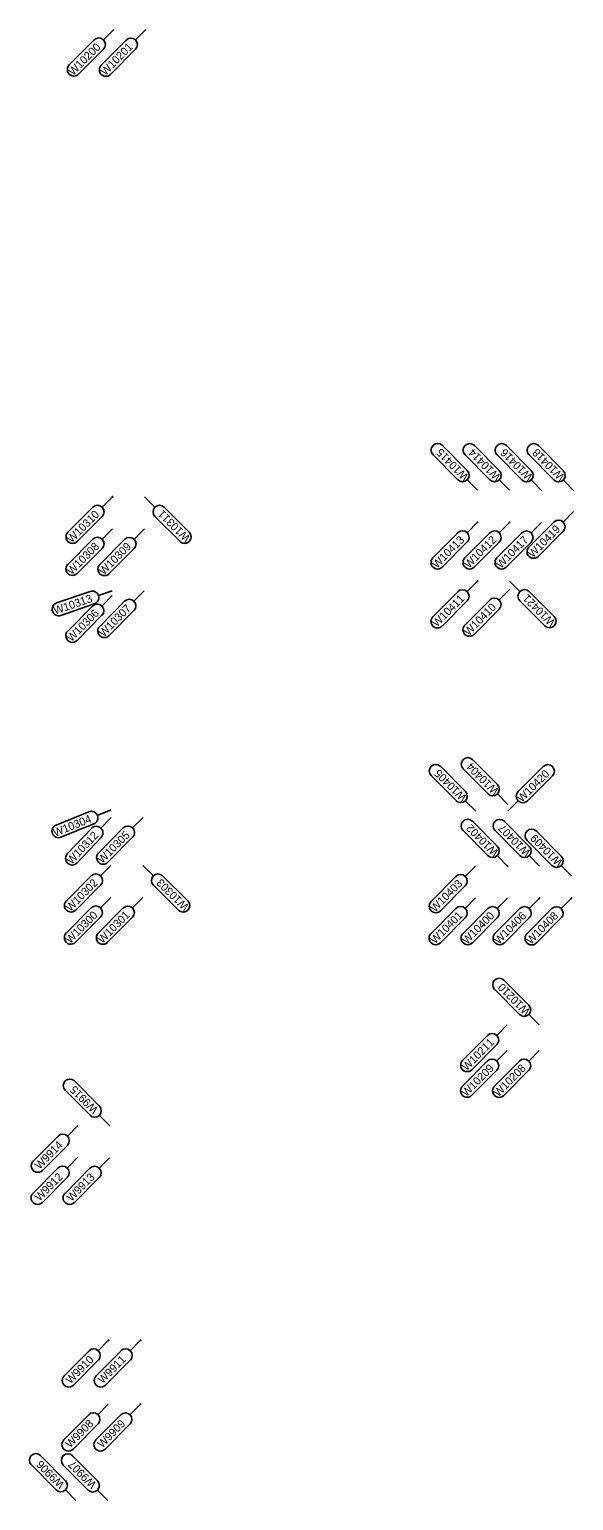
# Model space of a CAD drawing. Extents: x 12479652 to 12487250, y 9842710 to 9846560.
# Drawn here: x 12483667.3 to 12483752.3, y 9845145.7 to 9845375.4 of the extents above; entities that cross this region are included whole.
import ezdxf

# ---------------------------------------------------------------- set-up
doc = ezdxf.new("R2010")
doc.units = 0
doc.layers.add('Default', color=7, linetype='Continuous')
doc.layers.add('TextAlignmentLrg', color=7, linetype='Continuous')

msp = doc.modelspace()

# ---------------------------------------------------------------- linework, layer by layer
at = {"layer": 'Default'}
for p, q in [((12483673.52, 9845369.86), (12483677.41, 9845373.77)), ((12483678.52, 9845369.84), (12483682.41, 9845373.75)), ((12483680.48, 9845375.41), (12483678.86, 9845373.78)), ((12483685.48, 9845375.39), (12483683.86, 9845373.76)), ((12483678.87, 9845372.33), (12483674.98, 9845368.42)), ((12483683.87, 9845372.31), (12483679.98, 9845368.39)), ((12483735.7, 9845306.53), (12483731.82, 9845310.44)), ((12483740.7, 9845306.52), (12483736.82, 9845310.44)), ((12483745.7, 9845306.51), (12483741.82, 9845310.43)), ((12483750.7, 9845306.51), (12483746.82, 9845310.42)), ((12483730.36, 9845309), (12483734.25, 9845305.08)), ((12483735.36, 9845308.99), (12483739.25, 9845305.08)), ((12483740.36, 9845308.98), (12483744.25, 9845305.07)), ((12483745.36, 9845308.97), (12483749.25, 9845305.06)), ((12483737.32, 9845303.45), (12483735.7, 9845305.08)), ((12483742.32, 9845303.44), (12483740.7, 9845305.07)), ((12483747.32, 9845303.43), (12483745.7, 9845305.06)), ((12483752.32, 9845303.42), (12483750.7, 9845305.06)), ((12483680.27, 9845302.43), (12483678.65, 9845300.8)), ((12483685.27, 9845302.42), (12483686.9, 9845300.8)), ((12483673.31, 9845296.88), (12483677.2, 9845300.79)), ((12483688.35, 9845300.8), (12483692.26, 9845296.91)), ((12483752.32, 9845300.12), (12483750.69, 9845298.49)), ((12483678.65, 9845299.35), (12483674.76, 9845295.44)), ((12483690.82, 9845295.46), (12483686.91, 9845299.35)), ((12483737.31, 9845298.45), (12483735.69, 9845296.82)), ((12483742.31, 9845298.44), (12483740.69, 9845296.81)), ((12483745.35, 9845294.57), (12483749.24, 9845298.48)), ((12483747.31, 9845298.43), (12483745.69, 9845296.8)), ((12483673.3, 9845291.88), (12483677.19, 9845295.79)), ((12483678.3, 9845291.87), (12483682.19, 9845295.79)), ((12483680.26, 9845297.43), (12483678.64, 9845295.8)), ((12483685.26, 9845297.42), (12483683.64, 9845295.79)), ((12483730.35, 9845292.9), (12483734.24, 9845296.81)), ((12483735.7, 9845295.37), (12483731.81, 9845291.45)), ((12483735.35, 9845292.89), (12483739.24, 9845296.8)), ((12483740.7, 9845295.36), (12483736.81, 9845291.45)), ((12483740.35, 9845292.88), (12483744.24, 9845296.8)), ((12483745.7, 9845295.35), (12483741.81, 9845291.44)), ((12483750.7, 9845297.04), (12483746.81, 9845293.13)), ((12483678.65, 9845294.35), (12483674.76, 9845290.44)), ((12483683.65, 9845294.34), (12483679.76, 9845290.43)), ((12483737.3, 9845289.25), (12483735.68, 9845287.62)), ((12483742.3, 9845289.24), (12483743.93, 9845287.62)), ((12483671.54, 9845285.85), (12483676.76, 9845287.65)), ((12483680.23, 9845287.76), (12483678.06, 9845287.01)), ((12483680.23, 9845287), (12483678.61, 9845285.37)), ((12483685.23, 9845287.74), (12483683.61, 9845286.11)), ((12483730.34, 9845283.7), (12483734.23, 9845287.61)), ((12483735.68, 9845286.17), (12483731.79, 9845282.25)), ((12483735.34, 9845282.4), (12483739.23, 9845286.31)), ((12483742.3, 9845287.95), (12483740.68, 9845286.32)), ((12483747.85, 9845282.28), (12483743.94, 9845286.17)), ((12483745.38, 9845287.62), (12483749.29, 9845283.73)), ((12483677.42, 9845285.71), (12483672.21, 9845283.91)), ((12483673.27, 9845281.45), (12483677.16, 9845285.36)), ((12483678.61, 9845283.92), (12483674.73, 9845280)), ((12483678.27, 9845282.2), (12483682.16, 9845286.11)), ((12483683.62, 9845284.66), (12483679.73, 9845280.75)), ((12483740.68, 9845284.86), (12483736.79, 9845280.95)), ((12483740.41, 9845257.48), (12483736.52, 9845261.39)), ((12483730.06, 9845258.89), (12483733.95, 9845254.98)), ((12483735.41, 9845256.43), (12483731.52, 9845260.34)), ((12483735.07, 9845259.94), (12483738.96, 9845256.03)), ((12483747.58, 9845260.3), (12483743.66, 9845256.41)), ((12483745.11, 9845254.95), (12483749.02, 9845258.84)), ((12483737.03, 9845253.34), (12483735.4, 9845254.97)), ((12483742.03, 9845254.39), (12483740.41, 9845256.02)), ((12483742.03, 9845253.34), (12483743.66, 9845254.96)), ((12483671.45, 9845251.17), (12483676.57, 9845253.24)), ((12483680.04, 9845253.53), (12483677.9, 9845252.67)), ((12483680.04, 9845252.36), (12483678.45, 9845250.69)), ((12483685.04, 9845252.35), (12483683.41, 9845250.72)), ((12483740.4, 9845247.85), (12483736.51, 9845251.76)), ((12483745.4, 9845247.84), (12483741.51, 9845251.75)), ((12483677.34, 9845251.34), (12483672.22, 9845249.27)), ((12483673.2, 9845246.65), (12483677, 9845250.65)), ((12483678.07, 9845246.8), (12483681.96, 9845250.72)), ((12483735.05, 9845250.32), (12483738.94, 9845246.4)), ((12483740.05, 9845250.31), (12483743.94, 9845246.39)), ((12483750.39, 9845246.31), (12483746.5, 9845250.22)), ((12483678.49, 9845249.24), (12483674.69, 9845245.24)), ((12483683.42, 9845249.27), (12483679.53, 9845245.36)), ((12483745.05, 9845248.77), (12483748.94, 9845244.86)), ((12483680.02, 9845244.86), (12483678.4, 9845243.23)), ((12483685.02, 9845244.85), (12483686.66, 9845243.23)), ((12483742.01, 9845244.77), (12483740.39, 9845246.4)), ((12483747.01, 9845244.76), (12483745.39, 9845246.39)), ((12483752.01, 9845243.22), (12483750.39, 9845244.85)), ((12483673.06, 9845239.31), (12483676.95, 9845243.23)), ((12483688.11, 9845243.24), (12483692.02, 9845239.35)), ((12483730.05, 9845239.23), (12483733.94, 9845243.14)), ((12483737.01, 9845244.77), (12483735.39, 9845243.14)), ((12483678.41, 9845241.78), (12483674.52, 9845237.87)), ((12483690.57, 9845237.89), (12483686.66, 9845241.78)), ((12483735.4, 9845241.69), (12483731.51, 9845237.78)), ((12483673.05, 9845234.31), (12483676.94, 9845238.23)), ((12483678.05, 9845234.31), (12483681.94, 9845238.22)), ((12483680.02, 9845239.86), (12483678.4, 9845238.23)), ((12483685.02, 9845239.85), (12483683.4, 9845238.22)), ((12483730.04, 9845234.23), (12483733.93, 9845238.14)), ((12483735.04, 9845234.22), (12483738.93, 9845238.13)), ((12483737.01, 9845239.78), (12483735.38, 9845238.15)), ((12483740.04, 9845234.21), (12483743.93, 9845238.12)), ((12483742.01, 9845239.77), (12483740.38, 9845238.14)), ((12483745.04, 9845234.2), (12483748.93, 9845238.12)), ((12483747.01, 9845239.76), (12483745.38, 9845238.13)), ((12483752.01, 9845239.75), (12483750.38, 9845238.12)), ((12483678.4, 9845236.78), (12483674.51, 9845232.87)), ((12483683.4, 9845236.77), (12483679.51, 9845232.86)), ((12483735.39, 9845236.7), (12483731.5, 9845232.78)), ((12483740.39, 9845236.68), (12483736.5, 9845232.77)), ((12483745.39, 9845236.68), (12483741.5, 9845232.76)), ((12483750.39, 9845236.67), (12483746.5, 9845232.76)), ((12483745.33, 9845223.03), (12483741.44, 9845226.94)), ((12483739.99, 9845225.5), (12483743.87, 9845221.58)), ((12483741.95, 9845219.96), (12483740.33, 9845218.33)), ((12483746.95, 9845219.95), (12483745.33, 9845221.58)), ((12483734.98, 9845214.42), (12483738.87, 9845218.33)), ((12483740.33, 9845216.88), (12483736.44, 9845212.97)), ((12483741.94, 9845215.96), (12483740.31, 9845214.33)), ((12483746.94, 9845215.95), (12483745.31, 9845214.32)), ((12483734.97, 9845210.42), (12483738.86, 9845214.33)), ((12483740.32, 9845212.88), (12483736.43, 9845208.97)), ((12483739.97, 9845210.4), (12483743.86, 9845214.31)), ((12483745.32, 9845212.87), (12483741.43, 9845208.95)), ((12483678.22, 9845207.29), (12483674.33, 9845211.21)), ((12483672.88, 9845209.76), (12483676.77, 9845205.85)), ((12483679.84, 9845204.21), (12483678.22, 9845205.84)), ((12483674.84, 9845204.24), (12483673.22, 9845202.61)), ((12483667.88, 9845198.69), (12483671.77, 9845202.6)), ((12483673.22, 9845201.15), (12483669.33, 9845197.24)), ((12483674.81, 9845199.24), (12483673.19, 9845197.61)), ((12483679.81, 9845199.21), (12483678.19, 9845197.58)), ((12483667.85, 9845193.69), (12483671.74, 9845197.6)), ((12483672.85, 9845193.66), (12483676.74, 9845197.58)), ((12483673.2, 9845196.15), (12483669.31, 9845192.24)), ((12483678.2, 9845196.13), (12483674.31, 9845192.22)), ((12483672.71, 9845165.17), (12483676.6, 9845169.08)), ((12483677.71, 9845165.16), (12483681.6, 9845169.07)), ((12483679.67, 9845170.72), (12483678.05, 9845169.08)), ((12483684.67, 9845170.71), (12483683.05, 9845169.08)), ((12483678.05, 9845167.63), (12483674.16, 9845163.72)), ((12483683.05, 9845167.63), (12483679.16, 9845163.71)), ((12483679.62, 9845160.72), (12483678, 9845159.08)), ((12483684.62, 9845160.71), (12483683, 9845159.08)), ((12483672.66, 9845155.17), (12483676.55, 9845159.08)), ((12483678, 9845157.63), (12483674.11, 9845153.72)), ((12483677.66, 9845155.16), (12483681.55, 9845159.07)), ((12483683, 9845157.63), (12483679.11, 9845153.71)), ((12483667.59, 9845151.26), (12483671.47, 9845147.34)), ((12483672.93, 9845148.79), (12483669.04, 9845152.7)), ((12483672.58, 9845151.23), (12483676.47, 9845147.32)), ((12483677.93, 9845148.77), (12483674.04, 9845152.68)), ((12483674.55, 9845145.71), (12483672.93, 9845147.34)), ((12483679.55, 9845145.68), (12483677.93, 9845147.31))]:
    msp.add_line(p, q, dxfattribs=at)
for centre, start, end in [((12483678.14, 9845373.05), 315.1702, 135.1702), ((12483683.14, 9845373.03), 315.1702, 135.1702), ((12483674.25, 9845369.14), 135.1702, 315.1702), ((12483679.25, 9845369.12), 135.1702, 315.1702), ((12483731.09, 9845309.72), 44.8253, 224.8253), ((12483736.09, 9845309.71), 44.8253, 224.8253), ((12483741.09, 9845309.7), 44.8253, 224.8253), ((12483746.09, 9845309.7), 44.8253, 224.8253), ((12483734.98, 9845305.81), 224.8253, 44.8253), ((12483739.98, 9845305.8), 224.8253, 44.8253), ((12483744.98, 9845305.79), 224.8253, 44.8253), ((12483749.98, 9845305.78), 224.8253, 44.8253), ((12483677.93, 9845300.07), 315.1702, 135.1702), ((12483687.63, 9845300.07), 45.1702, 225.1702), ((12483749.97, 9845297.76), 315.1702, 135.1702), ((12483674.04, 9845296.16), 135.1702, 315.1702), ((12483677.92, 9845295.07), 315.1702, 135.1702), ((12483682.92, 9845295.06), 315.1702, 135.1702), ((12483691.54, 9845296.18), 225.1702, 45.1702), ((12483734.97, 9845296.09), 315.1702, 135.1702), ((12483739.97, 9845296.08), 315.1702, 135.1702), ((12483744.97, 9845296.07), 315.1702, 135.1702), ((12483746.08, 9845293.85), 135.1702, 315.1702), ((12483674.03, 9845291.16), 135.1702, 315.1702), ((12483679.03, 9845291.15), 135.1702, 315.1702), ((12483731.08, 9845292.18), 135.1702, 315.1702), ((12483736.08, 9845292.17), 135.1702, 315.1702), ((12483741.08, 9845292.16), 135.1702, 315.1702), ((12483677.09, 9845286.68), 289.0033, 109.0033), ((12483682.89, 9845285.39), 315.1702, 135.1702), ((12483734.95, 9845286.89), 315.1702, 135.1702), ((12483739.95, 9845285.59), 315.1702, 135.1702), ((12483744.66, 9845286.9), 45.1702, 225.1702), ((12483671.87, 9845284.88), 109.0033, 289.0033), ((12483677.89, 9845284.64), 315.1702, 135.1702), ((12483679, 9845281.47), 135.1702, 315.1702), ((12483731.07, 9845282.98), 135.1702, 315.1702), ((12483736.06, 9845281.68), 135.1702, 315.1702), ((12483748.57, 9845283.01), 225.1702, 45.1702), ((12483674, 9845280.73), 135.1702, 315.1702), ((12483735.79, 9845260.67), 44.8253, 224.8253), ((12483730.79, 9845259.61), 44.8253, 224.8253), ((12483748.3, 9845259.57), 314.8253, 134.8253), ((12483734.68, 9845255.7), 224.8253, 44.8253), ((12483739.68, 9845256.75), 224.8253, 44.8253), ((12483744.39, 9845255.68), 134.8253, 314.8253), ((12483676.95, 9845252.29), 291.9817, 111.9817), ((12483735.78, 9845251.04), 44.8253, 224.8253), ((12483740.78, 9845251.03), 44.8253, 224.8253), ((12483671.84, 9845250.22), 111.9817, 291.9817), ((12483677.75, 9845249.95), 316.4678, 136.4678), ((12483682.69, 9845249.99), 315.1702, 135.1702), ((12483745.78, 9845249.5), 44.8253, 224.8253), ((12483739.67, 9845247.13), 224.8253, 44.8253), ((12483744.67, 9845247.12), 224.8253, 44.8253), ((12483673.95, 9845245.95), 136.4678, 316.4678), ((12483678.8, 9845246.08), 135.1702, 315.1702), ((12483749.67, 9845245.58), 224.8253, 44.8253), ((12483677.68, 9845242.5), 315.1702, 135.1702), ((12483687.38, 9845242.51), 45.1702, 225.1702), ((12483734.67, 9845242.42), 315.1702, 135.1702), ((12483673.79, 9845238.59), 135.1702, 315.1702), ((12483677.67, 9845237.5), 315.1702, 135.1702), ((12483682.67, 9845237.49), 315.1702, 135.1702), ((12483691.3, 9845238.62), 225.1702, 45.1702), ((12483730.78, 9845238.5), 135.1702, 315.1702), ((12483734.66, 9845237.42), 315.1702, 135.1702), ((12483739.66, 9845237.41), 315.1702, 135.1702), ((12483744.66, 9845237.4), 315.1702, 135.1702), ((12483749.66, 9845237.39), 315.1702, 135.1702), ((12483673.78, 9845233.59), 135.1702, 315.1702), ((12483678.78, 9845233.58), 135.1702, 315.1702), ((12483730.77, 9845233.51), 135.1702, 315.1702), ((12483735.77, 9845233.5), 135.1702, 315.1702), ((12483740.77, 9845233.49), 135.1702, 315.1702), ((12483745.77, 9845233.48), 135.1702, 315.1702), ((12483740.71, 9845226.22), 44.8253, 224.8253), ((12483744.6, 9845222.31), 224.8253, 44.8253), ((12483739.6, 9845217.6), 315.1702, 135.1702), ((12483735.71, 9845213.69), 135.1702, 315.1702), ((12483739.59, 9845213.6), 315.1702, 135.1702), ((12483744.59, 9845213.59), 315.1702, 135.1702), ((12483673.6, 9845210.48), 44.8253, 224.8253), ((12483735.7, 9845209.69), 135.1702, 315.1702), ((12483740.7, 9845209.68), 135.1702, 315.1702), ((12483677.49, 9845206.57), 224.8253, 44.8253), ((12483672.49, 9845201.88), 315.1702, 135.1702), ((12483668.6, 9845197.97), 135.1702, 315.1702), ((12483672.47, 9845196.88), 315.1702, 135.1702), ((12483677.47, 9845196.85), 315.1702, 135.1702), ((12483668.58, 9845192.97), 135.1702, 315.1702), ((12483673.58, 9845192.94), 135.1702, 315.1702), ((12483677.33, 9845168.36), 315.1702, 135.1702), ((12483682.33, 9845168.35), 315.1702, 135.1702), ((12483673.44, 9845164.44), 135.1702, 315.1702), ((12483678.44, 9845164.44), 135.1702, 315.1702), ((12483677.28, 9845158.36), 315.1702, 135.1702), ((12483682.28, 9845158.35), 315.1702, 135.1702), ((12483668.31, 9845151.98), 44.8253, 224.8253), ((12483673.31, 9845151.96), 44.8253, 224.8253), ((12483673.39, 9845154.44), 135.1702, 315.1702), ((12483678.39, 9845154.44), 135.1702, 315.1702), ((12483672.2, 9845148.07), 224.8253, 44.8253), ((12483677.2, 9845148.04), 224.8253, 44.8253)]:
    msp.add_arc(centre, 1.03, start, end, dxfattribs=at)
at = {"layer": 'TextAlignmentLrg'}
for centre in [(12483680.27, 9845302.43), (12483737.32, 9845298.45), (12483742.31, 9845298.44), (12483737.3, 9845289.25), (12483742.01, 9845244.77), (12483747.01, 9845239.76), (12483752.01, 9845239.75), (12483679.67, 9845170.72), (12483684.67, 9845170.7), (12483684.62, 9845160.71)]:
    msp.add_circle(centre, 0.05, dxfattribs=at)

# ---------------------------------------------------------------- texts
at = {"layer": 'Default'}
for s, rotation, p in [('W10200', 45.1702, (12483674.13, 9845368.12)), ('W10201', 45.1702, (12483679.16, 9845368.13)), ('W10415', 134.8253, (12483736.01, 9845305.67)), ('W10414', 134.8253, (12483741.03, 9845305.64)), ('W10416', 134.8253, (12483746.02, 9845305.64)), ('W10418', 134.8253, (12483751.02, 9845305.64)), ('W10310', 45.1702, (12483673.92, 9845295.14)), ('W10311', 135.1702, (12483692.53, 9845296.1)), ('W10419', 45.1702, (12483745.96, 9845292.83)), ('W10413', 45.1702, (12483730.97, 9845291.16)), ('W10412', 45.1702, (12483735.98, 9845291.17)), ('W10417', 45.1702, (12483740.97, 9845291.15)), ('W10308', 45.1702, (12483673.91, 9845290.14)), ('W10309', 45.1702, (12483678.91, 9845290.13)), ('W10313', 19.0033, (12483671.33, 9845284.02)), ('W10411', 45.1702, (12483730.98, 9845281.99)), ('W10421', 135.1702, (12483749.56, 9845282.92)), ('W10306', 45.1702, (12483673.88, 9845279.7)), ('W10307', 45.1702, (12483678.89, 9845280.46)), ('W10410', 45.1702, (12483735.94, 9845280.65)), ('W10405', 134.8253, (12483735.71, 9845255.57)), ('W10404', 134.8253, (12483740.73, 9845256.6)), ('W10420', 44.8253, (12483744.24, 9845254.64)), ('W10304', 21.9817, (12483671.32, 9845249.33)), ('W10312', 46.4678, (12483673.87, 9845244.94)), ('W10305', 45.1702, (12483678.69, 9845245.07)), ('W10402', 134.8253, (12483740.69, 9845247)), ('W10407', 134.8253, (12483745.7, 9845246.98)), ('W10409', 134.8253, (12483750.71, 9845245.44)), ('W10302', 45.1702, (12483673.69, 9845237.59)), ('W10303', 135.1702, (12483692.31, 9845238.51)), ('W10403', 45.1702, (12483730.67, 9845237.49)), ('W10300', 45.1702, (12483673.66, 9845232.57)), ('W10301', 45.1702, (12483678.7, 9845232.6)), ('W10401', 45.1702, (12483730.69, 9845232.52)), ('W10400', 45.1702, (12483735.65, 9845232.47)), ('W10406', 45.1702, (12483740.65, 9845232.46)), ('W10408', 45.1702, (12483745.65, 9845232.46)), ('W10210', 134.8253, (12483745.64, 9845222.16)), ('W10211', 45.1702, (12483735.63, 9845212.71)), ('W10209', 45.1702, (12483735.58, 9845208.67)), ('W10208', 45.1702, (12483740.58, 9845208.66)), ('W9915', 134.8253, (12483678.13, 9845206.83)), ('W9914', 45.1702, (12483668.87, 9845197.33)), ('W9912', 45.1702, (12483668.87, 9845192.36)), ('W9913', 45.1702, (12483673.86, 9845192.32)), ('W9910', 45.1702, (12483673.71, 9845163.81)), ('W9911', 45.1702, (12483678.74, 9845163.84)), ('W9908', 45.1702, (12483673.66, 9845153.82)), ('W9909', 45.1702, (12483678.66, 9845153.81)), ('W9906', 134.8253, (12483672.86, 9845148.31)), ('W9907', 134.8253, (12483677.84, 9845148.3))]:
    msp.add_text(s, height=1.25, rotation=rotation, dxfattribs=at).set_placement(p)

doc.saveas('drawing.dxf')
